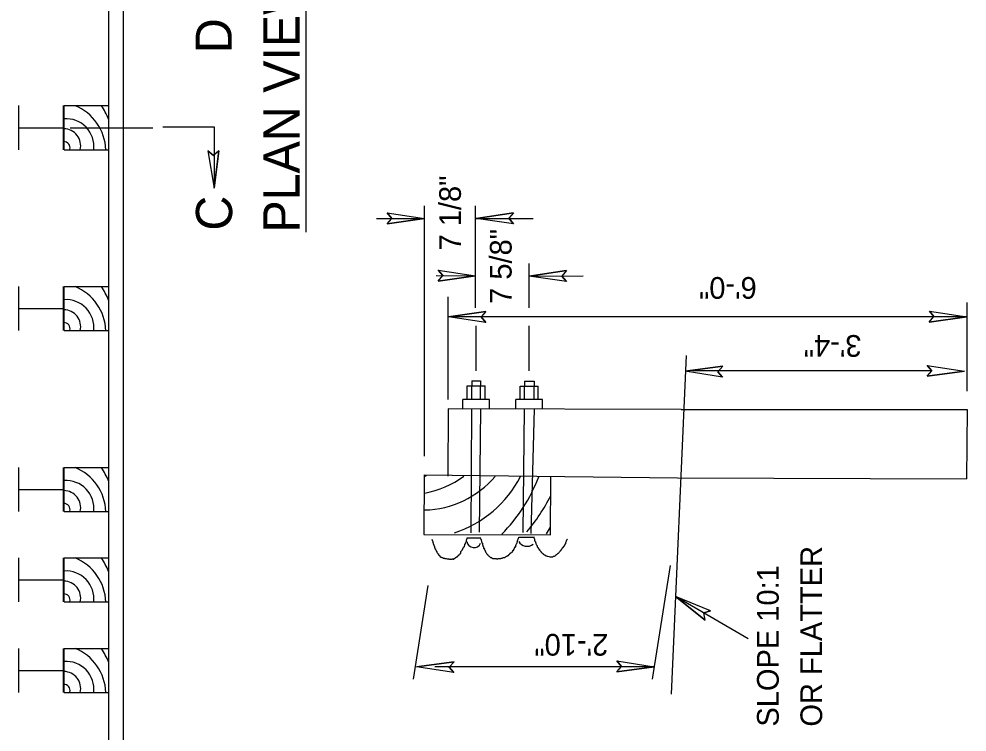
# Model space of a CAD drawing. Extents: x 12.2 to 54.5, y -7.8 to 16.1.
# Drawn here: x 50.1 to 52.721, y -3.502 to -1.531 of the extents above; entities that cross this region are included whole.
import ezdxf

# ---------------------------------------------------------------- set-up
doc = ezdxf.new("R2010")
doc.units = 0
for name, color, linetype in [('DETL-DIMS', 7, 'Continuous'), ('DETL-LINE', 7, 'Continuous'), ('DETL-NOTE', 7, 'Continuous'), ('DETL-PATT', 7, 'Continuous'), ('DETL-TITL', 7, 'Continuous')]:
    doc.layers.add(name, color=color, linetype=linetype)

msp = doc.modelspace()

# ---------------------------------------------------------------- linework, layer by layer
at = {"layer": 'DETL-DIMS'}
for p, q in [((50.1004, -1.832), (50.1004, -1.832)), ((50.1004, -1.832), (50.1004, -1.832)), ((50.2419, -1.8327), (50.4707, -1.8327)), ((50.4979, -1.8298), (50.6395, -1.8298)), ((50.6395, -1.8301), (50.6395, -1.9994)), ((50.6228, -1.8963), (50.6395, -1.9994)), ((50.6228, -1.8963), (50.6381, -1.9089)), ((50.653, -1.8958), (50.6381, -1.9089)), ((50.653, -1.8958), (50.6395, -1.9994)), ((51.1182, -2.0677), (51.2214, -2.0829)), ((51.1182, -2.0677), (51.1311, -2.0829)), ((51.2214, -2.7401), (51.2214, -2.0479)), ((51.3622, -2.3297), (51.3622, -2.0479)), ((51.4673, -2.0672), (51.3641, -2.0829)), ((51.4673, -2.0672), (51.4545, -2.0824)), ((51.0887, -2.0828), (51.2214, -2.0829)), ((51.1182, -2.0979), (51.2214, -2.0829)), ((51.1182, -2.0979), (51.1311, -2.0829)), ((51.4675, -2.0974), (51.3641, -2.0829)), ((51.3641, -2.0829), (51.5213, -2.0829)), ((51.4675, -2.0974), (51.4545, -2.0824)), ((51.2589, -2.2258), (51.3622, -2.241)), ((51.2589, -2.2258), (51.2718, -2.2409)), ((51.5105, -2.3297), (51.5105, -2.2076)), ((51.6137, -2.2268), (51.5105, -2.2426)), ((51.6137, -2.2268), (51.6008, -2.242)), ((51.2534, -2.2409), (51.3622, -2.241)), ((51.2589, -2.256), (51.2718, -2.2409)), ((51.2589, -2.256), (51.3622, -2.241)), ((51.5105, -2.2426), (51.6601, -2.2416)), ((51.6139, -2.257), (51.5105, -2.2426)), ((51.6139, -2.257), (51.6008, -2.242)), ((51.2866, -2.583), (51.2866, -2.2995)), ((50.1004, -2.332), (50.1004, -2.332)), ((50.1004, -2.332), (50.1004, -2.332)), ((52.7206, -2.5605), (52.7206, -2.3147)), ((52.7196, -2.3547), (51.2866, -2.3547)), ((51.3911, -2.3402), (51.2877, -2.3547)), ((51.3909, -2.3704), (51.2877, -2.3547)), ((51.3911, -2.3402), (51.378, -2.3552)), ((51.3909, -2.3704), (51.378, -2.3552)), ((52.6162, -2.3692), (52.6292, -2.3542)), ((52.6162, -2.3692), (52.7196, -2.3547)), ((52.6164, -2.3391), (52.7196, -2.3547)), ((52.6164, -2.3391), (52.6292, -2.3542)), ((51.3641, -2.5038), (51.3641, -2.3797)), ((51.5105, -2.5038), (51.5105, -2.3797)), ((52.6105, -2.489), (52.7137, -2.5053)), ((52.6105, -2.489), (52.6232, -2.5042)), ((52.0453, -2.4915), (51.9419, -2.5053)), ((52.045, -2.5216), (51.9419, -2.5053)), ((52.6232, -2.5042), (51.9622, -2.5036)), ((52.0453, -2.4915), (52.0322, -2.5064)), ((52.045, -2.5216), (52.0322, -2.5064)), ((52.6102, -2.5192), (52.6232, -2.5042)), ((52.6102, -2.5192), (52.7137, -2.5053)), ((50.1004, -2.832), (50.1004, -2.832)), ((50.1004, -2.832), (50.1004, -2.832)), ((51.9, -3.0422), (51.8503, -3.3565)), ((50.1004, -3.082), (50.1004, -3.082)), ((50.1004, -3.082), (50.1004, -3.082)), ((51.2306, -3.0975), (51.1901, -3.3565)), ((51.9965, -3.1929), (51.9149, -3.1277)), ((52.0117, -3.1669), (51.9149, -3.1277)), ((52.1155, -3.2448), (51.9149, -3.1277)), ((52.0117, -3.1669), (51.9929, -3.1733)), ((51.9965, -3.1929), (51.9929, -3.1733)), ((51.3028, -3.3081), (51.1994, -3.3219)), ((51.3025, -3.3382), (51.1994, -3.3219)), ((51.8558, -3.3219), (51.2501, -3.3219)), ((51.3028, -3.3081), (51.2897, -3.323)), ((51.3025, -3.3382), (51.2897, -3.323)), ((51.7523, -3.3358), (51.7653, -3.3208)), ((51.7523, -3.3358), (51.8558, -3.3219)), ((51.7526, -3.3056), (51.8558, -3.3219)), ((51.7526, -3.3056), (51.7653, -3.3208)), ((50.1004, -3.332), (50.1004, -3.332)), ((50.1004, -3.332), (50.1004, -3.332))]:
    msp.add_line(p, q, dxfattribs=at)
for points in [[(50.6228, -1.8963), (50.6395, -1.9994), (50.653, -1.8958), (50.6381, -1.9089)], [(51.1182, -2.0677), (51.2214, -2.0829), (51.1182, -2.0979), (51.1311, -2.0829)], [(51.4675, -2.0974), (51.3641, -2.0829), (51.4673, -2.0672), (51.4545, -2.0824)], [(51.2589, -2.2258), (51.3622, -2.241), (51.2589, -2.256), (51.2718, -2.2409)], [(51.6139, -2.257), (51.5105, -2.2426), (51.6137, -2.2268), (51.6008, -2.242)], [(51.3909, -2.3704), (51.2877, -2.3547), (51.3911, -2.3402), (51.378, -2.3552)], [(52.6164, -2.3391), (52.7196, -2.3547), (52.6162, -2.3692), (52.6292, -2.3542)], [(52.6105, -2.489), (52.7137, -2.5053), (52.6102, -2.5192), (52.6232, -2.5042)], [(52.045, -2.5216), (51.9419, -2.5053), (52.0453, -2.4915), (52.0322, -2.5064)], [(52.0117, -3.1669), (51.9149, -3.1277), (51.9965, -3.1929), (51.9929, -3.1733)], [(51.3025, -3.3382), (51.1994, -3.3219), (51.3028, -3.3081), (51.2897, -3.323)], [(51.7526, -3.3056), (51.8558, -3.3219), (51.7523, -3.3358), (51.7653, -3.3208)]]:
    msp.add_lwpolyline(points, close=True, dxfattribs=at)
at = {"layer": 'DETL-LINE'}
for p, q in [((50.3897, -5.332), (50.3897, 2.7851)), ((50.3485, -5.332), (50.3485, 2.7601)), ((50.1004, -1.8929), (50.1004, -1.771)), ((50.223, -1.8929), (50.223, -1.771)), ((50.225, -1.8929), (50.225, -1.771)), ((50.225, -1.771), (50.3485, -1.771)), ((50.3485, -1.8929), (50.3485, -1.771)), ((50.1004, -1.832), (50.223, -1.832)), ((50.3485, -1.832), (50.3485, -1.832)), ((50.225, -1.8929), (50.3485, -1.8929)), ((50.1004, -2.3929), (50.1004, -2.271)), ((50.223, -2.3929), (50.223, -2.271)), ((50.225, -2.3929), (50.225, -2.271)), ((50.225, -2.271), (50.3485, -2.271)), ((50.3485, -2.3929), (50.3485, -2.271)), ((50.1004, -2.332), (50.223, -2.332)), ((50.3485, -2.332), (50.3485, -2.332)), ((50.225, -2.3929), (50.3485, -2.3929)), ((51.9445, -2.4618), (51.9029, -3.3977)), ((51.3524, -2.5321), (51.3758, -2.5321)), ((51.3524, -2.5321), (51.3524, -2.5455)), ((51.3758, -2.5321), (51.3758, -2.5455)), ((51.4972, -2.5326), (51.5238, -2.5326)), ((51.4972, -2.5326), (51.4972, -2.546)), ((51.5238, -2.5326), (51.5238, -2.546)), ((51.3392, -2.5455), (51.389, -2.5455)), ((51.3392, -2.5829), (51.3392, -2.5455)), ((51.3524, -2.5829), (51.3524, -2.5455)), ((51.3758, -2.5829), (51.3758, -2.5455)), ((51.389, -2.5829), (51.389, -2.5455)), ((51.4856, -2.5834), (51.4856, -2.546)), ((51.4856, -2.546), (51.5354, -2.546)), ((51.4972, -2.5834), (51.4972, -2.546)), ((51.5238, -2.5834), (51.5238, -2.546)), ((51.5354, -2.5834), (51.5354, -2.546)), ((51.4007, -2.5829), (51.3275, -2.5829)), ((51.3275, -2.6089), (51.3275, -2.5829)), ((51.4007, -2.6089), (51.4007, -2.5829)), ((51.4739, -2.6094), (51.4739, -2.5834)), ((51.5471, -2.5834), (51.4739, -2.5834)), ((51.5471, -2.6094), (51.5471, -2.5834)), ((51.2866, -2.6089), (51.2853, -2.7956)), ((51.9306, -2.611), (51.2866, -2.6089)), ((51.35, -2.952), (51.3524, -2.6093)), ((51.3758, -2.6094), (51.3718, -2.9499)), ((51.4934, -2.9505), (51.4972, -2.6098)), ((51.5238, -2.6099), (51.5152, -2.9538)), ((51.9306, -2.611), (52.7206, -2.6105)), ((52.7206, -2.6105), (52.7188, -2.8025)), ((50.1004, -2.8929), (50.1004, -2.771)), ((50.223, -2.8929), (50.223, -2.771)), ((50.225, -2.8929), (50.225, -2.771)), ((50.225, -2.771), (50.3485, -2.771)), ((50.3485, -2.8929), (50.3485, -2.771)), ((51.2198, -2.7917), (51.2191, -2.9561)), ((51.2198, -2.7917), (51.9202, -2.8001)), ((51.5692, -2.9574), (51.5707, -2.7972)), ((51.9202, -2.8001), (52.7188, -2.8025)), ((50.1004, -2.832), (50.223, -2.832)), ((50.3485, -2.832), (50.3485, -2.832)), ((50.225, -2.8929), (50.3485, -2.8929)), ((51.2191, -2.9561), (51.5692, -2.9574)), ((51.3397, -2.9653), (51.3766, -2.9653)), ((51.4816, -2.9634), (51.5247, -2.9634)), ((50.1004, -3.1429), (50.1004, -3.021)), ((50.223, -3.1429), (50.223, -3.021)), ((50.225, -3.1429), (50.225, -3.021)), ((50.225, -3.021), (50.3485, -3.021)), ((50.3485, -3.1429), (50.3485, -3.021)), ((50.1004, -3.082), (50.223, -3.082)), ((50.3485, -3.082), (50.3485, -3.082)), ((50.225, -3.1429), (50.3485, -3.1429)), ((50.1004, -3.3929), (50.1004, -3.271)), ((50.223, -3.3929), (50.223, -3.271)), ((50.225, -3.3929), (50.225, -3.271)), ((50.225, -3.271), (50.3485, -3.271)), ((50.3485, -3.3929), (50.3485, -3.271)), ((50.1004, -3.332), (50.223, -3.332)), ((50.3485, -3.332), (50.3485, -3.332)), ((50.225, -3.3929), (50.3485, -3.3929))]:
    msp.add_line(p, q, dxfattribs=at)
for centre, radius, start, end in [((51.3579, -2.9727), 0.02, 188.3494, 336.752), ((51.5049, -2.9621), 0.0269, 209.5517, 308.2673)]:
    msp.add_arc(centre, radius, start, end, dxfattribs=at)
for points in [[(51.2416, -2.9689), (51.2436, -2.9746), (51.2441, -2.9774), (51.245, -2.9798), (51.246, -2.9836), (51.2469, -2.9841), (51.247, -2.9859), (51.2475, -2.9874), (51.2479, -2.9894), (51.2484, -2.9894), (51.2484, -2.9912), (51.2498, -2.9932), (51.2498, -2.9946), (51.2508, -2.996), (51.2513, -2.9959), (51.2523, -2.9998), (51.2533, -3.0007), (51.2533, -3.0012), (51.2537, -3.0027), (51.2546, -3.0027), (51.2551, -3.0041), (51.2556, -3.006), (51.2566, -3.006), (51.2566, -3.0074), (51.2576, -3.0089), (51.2581, -3.0094), (51.2586, -3.0102), (51.2594, -3.0102), (51.2594, -3.0117), (51.2609, -3.0136), (51.2624, -3.0145), (51.2633, -3.015), (51.2638, -3.0169), (51.2652, -3.0179), (51.2652, -3.0184), (51.2667, -3.0193), (51.2686, -3.0197), (51.27, -3.0202), (51.2719, -3.0207), (51.2724, -3.0211), (51.2738, -3.0216), (51.2767, -3.0216), (51.2777, -3.0226), (51.2795, -3.0226), (51.2834, -3.0235), (51.2867, -3.0235), (51.2877, -3.024), (51.2882, -3.024), (51.2895, -3.0243), (51.291, -3.024), (51.2924, -3.0243), (51.2943, -3.0243), (51.2972, -3.0243), (51.2991, -3.0239), (51.3019, -3.0243), (51.3033, -3.0224), (51.3048, -3.0224), (51.3062, -3.0209), (51.3077, -3.0204), (51.308, -3.0194), (51.31, -3.0191), (51.311, -3.0176), (51.3115, -3.0181), (51.3128, -3.0166), (51.3128, -3.0161), (51.3142, -3.0151), (51.3142, -3.0146), (51.3157, -3.0137), (51.3152, -3.0133), (51.3171, -3.0123), (51.3195, -3.0098), (51.3194, -3.0085), (51.3209, -3.0085), (51.3219, -3.006), (51.3232, -3.0012), (51.3247, -3.0007), (51.3256, -2.9984), (51.3266, -2.9979), (51.3271, -2.995), (51.3284, -2.9931), (51.3294, -2.9912), (51.3308, -2.9906), (51.3326, -2.984), (51.3336, -2.9825), (51.3341, -2.9821), (51.3345, -2.9811), (51.3355, -2.9778), (51.3369, -2.9745), (51.3369, -2.9725), (51.3378, -2.9705), (51.3388, -2.9677), (51.3397, -2.9653), (51.3402, -2.9649)], [(51.3764, -2.967), (51.3759, -2.967), (51.3768, -2.9694), (51.3778, -2.9703), (51.3783, -2.9737), (51.3788, -2.9755), (51.3793, -2.9775), (51.3803, -2.9803), (51.3813, -2.9803), (51.3813, -2.9837), (51.3817, -2.9855), (51.3827, -2.9855), (51.3822, -2.987), (51.3831, -2.9899), (51.3841, -2.9903), (51.3842, -2.9932), (51.3851, -2.9947), (51.3861, -2.9951), (51.3865, -2.9975), (51.387, -2.999), (51.388, -2.9994), (51.3885, -3.0003), (51.3885, -3.0018), (51.39, -3.0032), (51.39, -3.0046), (51.3909, -3.006), (51.3928, -3.009), (51.3938, -3.0108), (51.3947, -3.0113), (51.3952, -3.0122), (51.3961, -3.0127), (51.3976, -3.0146), (51.4005, -3.0175), (51.4024, -3.0189), (51.4038, -3.0198), (51.4058, -3.0198), (51.4071, -3.0212), (51.4129, -3.0227), (51.4153, -3.0227), (51.4167, -3.0231), (51.4196, -3.0231), (51.4209, -3.0236), (51.4229, -3.0235), (51.4243, -3.0231), (51.4291, -3.023), (51.4305, -3.0225), (51.4319, -3.0225), (51.4348, -3.0215), (51.4362, -3.0215), (51.4367, -3.021), (51.4376, -3.021), (51.4419, -3.0195), (51.4434, -3.0195), (51.4448, -3.0186), (51.4452, -3.0182), (51.4491, -3.0162), (51.4504, -3.0152), (51.4504, -3.0147), (51.4519, -3.0147), (51.4538, -3.0128), (51.4552, -3.0113), (51.4566, -3.0104), (51.4566, -3.0095), (51.4581, -3.009), (51.459, -3.0075), (51.4599, -3.0075), (51.4614, -3.0055), (51.4638, -3.0051), (51.4651, -3.0017), (51.4665, -2.9994), (51.468, -2.9994), (51.468, -2.9979), (51.4685, -2.9964), (51.4695, -2.9964), (51.4694, -2.995), (51.4698, -2.9936), (51.4708, -2.9921), (51.4718, -2.9902), (51.4723, -2.9907), (51.4737, -2.9883), (51.4737, -2.9864), (51.4742, -2.9849), (51.475, -2.9826), (51.476, -2.9811), (51.4765, -2.9801), (51.4774, -2.9778), (51.4779, -2.9763), (51.4784, -2.974), (51.4797, -2.9692), (51.4807, -2.9672), (51.4816, -2.9649), (51.4816, -2.9634)], [(51.5234, -2.964), (51.5244, -2.9674), (51.5254, -2.9688), (51.5254, -2.9721), (51.5259, -2.974), (51.5269, -2.9759), (51.5278, -2.9774), (51.5278, -2.9788), (51.5283, -2.9788), (51.5288, -2.9812), (51.5292, -2.9826), (51.5297, -2.9831), (51.5312, -2.9859), (51.5317, -2.9864), (51.5327, -2.9883), (51.5327, -2.9898), (51.5332, -2.9912), (51.534, -2.9911), (51.5346, -2.9931), (51.5355, -2.9936), (51.5365, -2.9959), (51.5375, -2.9969), (51.538, -2.9979), (51.5384, -2.9993), (51.5388, -2.9988), (51.5403, -3.0006), (51.5413, -3.0021), (51.5418, -3.0031), (51.5427, -3.0036), (51.5431, -3.0045), (51.5446, -3.0049), (51.5446, -3.0064), (51.5461, -3.0078), (51.548, -3.0093), (51.5494, -3.0106), (51.5509, -3.0116), (51.5519, -3.0121), (51.5523, -3.0126), (51.5537, -3.0126), (51.5542, -3.0135), (51.5551, -3.014), (51.5566, -3.0149), (51.5585, -3.0154), (51.5599, -3.0158), (51.5604, -3.0163), (51.5614, -3.0163), (51.5671, -3.0182), (51.5727, -3.0182), (51.5762, -3.0177), (51.5775, -3.0167), (51.5789, -3.0167), (51.5823, -3.0152), (51.5837, -3.0133), (51.5852, -3.0123), (51.5866, -3.0118), (51.5904, -3.008), (51.5927, -3.0075), (51.5941, -3.0042), (51.597, -3.0017), (51.5979, -3.0003), (51.5984, -2.9998), (51.5994, -2.9984), (51.6008, -2.9969), (51.6036, -2.9926), (51.6046, -2.9921), (51.605, -2.9907), (51.606, -2.9888), (51.6079, -2.9878), (51.6083, -2.9864), (51.6093, -2.9849), (51.6103, -2.9825), (51.6116, -2.9816), (51.6121, -2.9801), (51.6121, -2.9787), (51.6135, -2.9749), (51.6135, -2.973), (51.6149, -2.971), (51.6159, -2.9687), (51.6164, -2.9682)]]:
    msp.add_spline(points, degree=3, dxfattribs=at)
at = {"layer": 'DETL-PATT'}
for centre, radius, start, end in [((51.1776, -2.5919), 0.2538, 280.0268, 306.912), ((51.2163, -2.6269), 0.2617, 271.1987, 319.858), ((51.1543, -2.5659), 0.2391, 286.6952, 287.6506), ((51.2033, -2.6485), 0.3197, 288.3721, 332.445), ((51.111, -2.6346), 0.4557, 315.2141, 339.1469), ((51.0851, -2.5998), 0.5456, 320.1581, 332.7687), ((50.6424, -2.3815), 1.0804, 327.9748, 329.0858)]:
    msp.add_arc(centre, radius, start, end, dxfattribs=at)
for centre, major_axis, start_param, end_param in [((50.205, -1.8983), (0, 0.137), 4.750897, 5.899278), ((50.0724, -1.9372), (0, 0.3071), 5.144981, 5.283467), ((50.2309, -1.8844), (0, 0.0772), 4.600695, 6.361038), ((50.2243, -1.8823), (0, 0.0472), 4.485117, 6.270221), ((50.2243, -1.8879), (0, 0.0174), 4.485117, 6.270221), ((50.205, -2.3983), (0, 0.137), 4.750897, 5.899278), ((50.0724, -2.4372), (0, 0.3071), 5.144981, 5.283467), ((50.2309, -2.3844), (0, 0.0772), 4.600695, 6.361038), ((50.2243, -2.3823), (0, 0.0472), 4.485117, 6.270221), ((50.2243, -2.3879), (0, 0.0174), 4.485117, 6.270221), ((50.205, -2.8983), (0, 0.137), 4.750897, 5.899278), ((50.0724, -2.9372), (0, 0.3071), 5.144981, 5.283467), ((50.2309, -2.8844), (0, 0.0772), 4.600695, 6.361038), ((50.2243, -2.8823), (0, 0.0472), 4.485117, 6.270221), ((50.2243, -2.8879), (0, 0.0174), 4.485117, 6.270221), ((50.205, -3.1483), (0, 0.137), 4.750897, 5.899278), ((50.0724, -3.1872), (0, 0.3071), 5.144981, 5.283467), ((50.2309, -3.1344), (0, 0.0772), 4.600695, 6.361038), ((50.2243, -3.1323), (0, 0.0472), 4.485117, 6.270221), ((50.2243, -3.1379), (0, 0.0174), 4.485117, 6.270221), ((50.205, -3.3983), (0, 0.137), 4.750897, 5.899278), ((50.0724, -3.4372), (0, 0.3071), 5.144981, 5.283467), ((50.2309, -3.3844), (0, 0.0772), 4.600695, 6.361038), ((50.2243, -3.3823), (0, 0.0472), 4.485117, 6.270221), ((50.2243, -3.3879), (0, 0.0174), 4.485117, 6.270221)]:
    msp.add_ellipse(centre, major_axis=major_axis, ratio=0.989796, start_param=start_param, end_param=end_param, dxfattribs=at)
at = {"layer": 'DETL-TITL'}
msp.add_line((50.8942, -2.121), (50.8942, -1.25), dxfattribs=at)

# ---------------------------------------------------------------- texts
at = {"layer": 'DETL-NOTE'}
for s, rotation, p in [('7 1/8"', 90, (51.3218, -2.1712)), ('7 5/8"', 90, (51.4619, -2.3189)), ('6\'-0"', 180, (52.1395, -2.2448)), ('3\'-4"', 180, (52.429, -2.4052)), ('OR FLATTER', 90, (52.3201, -3.4873)), ('SLOPE 10:1', 90, (52.2001, -3.4873)), ('2\'-10"', 180, (51.7291, -3.2311))]:
    msp.add_text(s, height=0.06, rotation=rotation, dxfattribs=at).set_placement(p)
at = {"layer": 'DETL-TITL'}
for s, p in [('PLAN VIEW', (50.8757, -2.122)), ('D', (50.6886, -1.6261)), ('C', (50.6895, -2.1165))]:
    msp.add_text(s, height=0.1, rotation=90, dxfattribs=at).set_placement(p)

doc.saveas('drawing.dxf')
